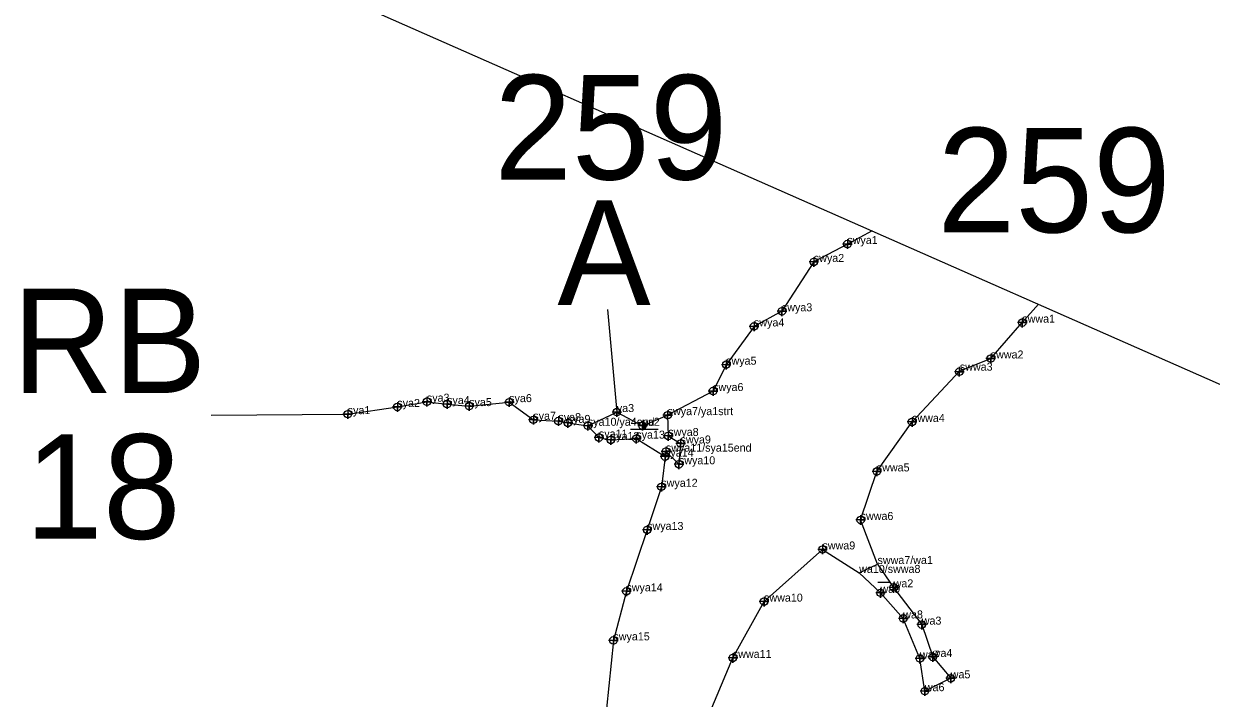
# Model space of a CAD drawing. Extents: x 2071991 to 2268989, y 436479 to 469629.
# Drawn here: x 2217583 to 2218325, y 438941 to 439363 of the extents above; entities that cross this region are included whole.
import ezdxf

# ---------------------------------------------------------------- set-up
doc = ezdxf.new("R2010")
doc.units = 0
for name, color, linetype in [('approx_PSA', 7, 'Continuous'), ('Default', 7, 'Continuous'), ('Exist Environmental Wetland Boundary', 7, 'Continuous'), ('Exist Environmental Wetland Boundary Cogo Comment', 7, 'Continuous'), ('Exist Environmental Wetland Boundary Cogo Point CELL', 7, 'Continuous'), ('Exist Hydro Jurisdictional Stream or Body of Water NEU Mitigable', 7, 'Continuous'), ('Exist Hydro Jurisdictional Stream or Body of Water NEU Mitigable Cogo Comment', 7, 'Continuous'), ('Exist Hydro Jurisdictional Stream or Body of Water NEU Mitigable Cogo Point CELL', 7, 'Continuous'), ('Exist Hydro Jurisdictional Stream or Body of Water NEU NonMitigable', 7, 'Continuous'), ('Exist Hydro Jurisdictional Stream or Body of Water NEU NonMitigable Cogo Comment', 7, 'Continuous'), ('Exist Hydro Jurisdictional Stream or Body of Water NEU NonMitigable Cogo Point CELL', 7, 'Continuous'), ('Exist Hydro Swamp or Marsh', 7, 'Continuous')]:
    doc.layers.add(name, color=color, linetype=linetype)

msp = doc.modelspace()

# ---------------------------------------------------------------- linework, layer by layer
at = {"layer": 'approx_PSA'}
msp.add_line((2217672.23, 439428.18), (2218953.94, 438862.92), dxfattribs=at)
at = {"layer": 'Default'}
for p, q in [((2217947.78, 439184.45), (2217953.67, 439120.41)), ((2217700.06, 439118.54), (2217785.49, 439119.1))]:
    msp.add_line(p, q, dxfattribs=at)
at = {"layer": 'Exist Environmental Wetland Boundary'}
for points in [[(2217935.6, 439111.83), (2217953.67, 439120.41), (2217969.69, 439111.83), (2217985.43, 439118.48)], [(2218116.61, 439025.41), (2218126.67, 439010.81), (2218144.24, 438987.52), (2218151.09, 438967.28), (2218162.35, 438953.95), (2218146.17, 438945.9), (2218143.11, 438966.31), (2218132.69, 438991.39), (2218118.45, 439007.36), (2218105.13, 439019.85)]]:
    msp.add_lwpolyline(points, dxfattribs=at)
at = {"layer": 'Exist Environmental Wetland Boundary Cogo Point CELL'}
for points in [[(2217953.67, 439123.41), (2217953.67, 439117.41), (2217953.67, 439120.41), (2217956.67, 439120.41), (2217950.67, 439120.41)], [(2217985.43, 439121.48), (2217985.43, 439115.48), (2217985.43, 439118.48), (2217988.43, 439118.48), (2217982.43, 439118.48)], [(2217935.6, 439114.83), (2217935.6, 439108.83), (2217935.6, 439111.83), (2217938.6, 439111.83), (2217932.6, 439111.83)], [(2217969.69, 439114.83), (2217969.69, 439108.83), (2217969.69, 439111.83), (2217972.69, 439111.83), (2217966.69, 439111.83)], [(2218118.45, 439010.36), (2218118.45, 439004.36), (2218118.45, 439007.36), (2218121.45, 439007.36), (2218115.45, 439007.36)], [(2218126.67, 439013.81), (2218126.67, 439007.81), (2218126.67, 439010.81), (2218129.67, 439010.81), (2218123.67, 439010.81)], [(2218132.69, 438994.39), (2218132.69, 438988.39), (2218132.69, 438991.39), (2218135.69, 438991.39), (2218129.69, 438991.39)], [(2218144.24, 438990.52), (2218144.24, 438984.52), (2218144.24, 438987.52), (2218147.24, 438987.52), (2218141.24, 438987.52)], [(2218143.11, 438969.31), (2218143.11, 438963.31), (2218143.11, 438966.31), (2218146.11, 438966.31), (2218140.11, 438966.31)], [(2218151.09, 438970.28), (2218151.09, 438964.28), (2218151.09, 438967.28), (2218154.09, 438967.28), (2218148.09, 438967.28)], [(2218162.35, 438956.95), (2218162.35, 438950.95), (2218162.35, 438953.95), (2218165.35, 438953.95), (2218159.35, 438953.95)], [(2218146.17, 438948.9), (2218146.17, 438942.9), (2218146.17, 438945.9), (2218149.17, 438945.9), (2218143.17, 438945.9)]]:
    msp.add_lwpolyline(points, dxfattribs=at)
for centre in [(2217953.67, 439120.41), (2217985.43, 439118.48), (2217935.6, 439111.83), (2217969.69, 439111.83), (2218118.45, 439007.36), (2218126.67, 439010.81), (2218132.69, 438991.39), (2218144.24, 438987.52), (2218143.11, 438966.31), (2218151.09, 438967.28), (2218162.35, 438953.95), (2218146.17, 438945.9)]:
    msp.add_circle(centre, 2.34, dxfattribs=at)
at = {"layer": 'Exist Hydro Jurisdictional Stream or Body of Water NEU Mitigable'}
msp.add_lwpolyline([(2217785.49, 439119.1), (2217816.49, 439123.6), (2217834.97, 439126.88), (2217847.6, 439125.41), (2217861.39, 439124.13), (2217886.41, 439126.61), (2217901.49, 439115.57), (2217917.15, 439114.79), (2217923.07, 439113.63), (2217935.6, 439111.83), (2217942.46, 439104.41), (2217949.93, 439102.96), (2217965.85, 439103.8), (2217983.84, 439092.54)], dxfattribs=at)
at = {"layer": 'Exist Hydro Jurisdictional Stream or Body of Water NEU Mitigable Cogo Point CELL'}
for points in [[(2217816.49, 439126.6), (2217816.49, 439120.6), (2217816.49, 439123.6), (2217819.49, 439123.6), (2217813.49, 439123.6)], [(2217834.97, 439129.88), (2217834.97, 439123.88), (2217834.97, 439126.88), (2217837.97, 439126.88), (2217831.97, 439126.88)], [(2217847.6, 439128.41), (2217847.6, 439122.41), (2217847.6, 439125.41), (2217850.6, 439125.41), (2217844.6, 439125.41)], [(2217861.39, 439127.13), (2217861.39, 439121.13), (2217861.39, 439124.13), (2217864.39, 439124.13), (2217858.39, 439124.13)], [(2217886.41, 439129.61), (2217886.41, 439123.61), (2217886.41, 439126.61), (2217889.41, 439126.61), (2217883.41, 439126.61)], [(2217785.49, 439122.1), (2217785.49, 439116.1), (2217785.49, 439119.1), (2217788.49, 439119.1), (2217782.49, 439119.1)], [(2217901.49, 439118.57), (2217901.49, 439112.57), (2217901.49, 439115.57), (2217904.49, 439115.57), (2217898.49, 439115.57)], [(2217917.15, 439117.79), (2217917.15, 439111.79), (2217917.15, 439114.79), (2217920.15, 439114.79), (2217914.15, 439114.79)], [(2217923.07, 439116.63), (2217923.07, 439110.63), (2217923.07, 439113.63), (2217926.07, 439113.63), (2217920.07, 439113.63)], [(2217942.46, 439107.41), (2217942.46, 439101.41), (2217942.46, 439104.41), (2217945.46, 439104.41), (2217939.46, 439104.41)], [(2217949.93, 439105.96), (2217949.93, 439099.96), (2217949.93, 439102.96), (2217952.93, 439102.96), (2217946.93, 439102.96)], [(2217965.85, 439106.8), (2217965.85, 439100.8), (2217965.85, 439103.8), (2217968.85, 439103.8), (2217962.85, 439103.8)], [(2217985.84, 439108.48), (2217985.84, 439102.48), (2217985.84, 439105.48), (2217988.84, 439105.48), (2217982.84, 439105.48)]]:
    msp.add_lwpolyline(points, dxfattribs=at)
for centre in [(2217834.97, 439126.88), (2217847.6, 439125.41), (2217861.39, 439124.13), (2217886.41, 439126.61), (2217785.49, 439119.1), (2217816.49, 439123.6), (2217901.49, 439115.57), (2217917.15, 439114.79), (2217923.07, 439113.63), (2217942.46, 439104.41), (2217949.93, 439102.96), (2217965.85, 439103.8), (2217985.84, 439105.48)]:
    msp.add_circle(centre, 2.34, dxfattribs=at)
at = {"layer": 'Exist Hydro Jurisdictional Stream or Body of Water NEU NonMitigable'}
for points in [[(2218113.17, 439233.72), (2218097.74, 439225.46), (2218076.79, 439214.25), (2218056.84, 439183.41), (2218039.4, 439173.95), (2218022, 439150.03), (2218013.84, 439133.54), (2217985.43, 439118.48), (2217985.84, 439105.48), (2217993.48, 439100.76), (2217992.49, 439087.76), (2217984.34, 439095.66)], [(2218012.02, 438933.04), (2218026.19, 438966.68), (2218045.69, 439001.9), (2218082.21, 439034.51), (2218105.13, 439019.85), (2218116.61, 439025.41), (2218106.05, 439052.94), (2218116.16, 439083.3), (2218138.17, 439114.21), (2218168.06, 439146.26), (2218187.36, 439153.91), (2218207.08, 439176.31), (2218217.22, 439187.83)], [(2217983.84, 439092.54), (2217984.34, 439095.66), (2217981.49, 439073.67), (2217972.61, 439046.71), (2217959.66, 439008.34), (2217951.55, 438977.67), (2217947.25, 438934.98)]]:
    msp.add_lwpolyline(points, dxfattribs=at)
at = {"layer": 'Exist Hydro Jurisdictional Stream or Body of Water NEU NonMitigable Cogo Point CELL'}
for points in [[(2218097.74, 439228.46), (2218097.74, 439222.46), (2218097.74, 439225.46), (2218100.74, 439225.46), (2218094.74, 439225.46)], [(2218076.79, 439217.25), (2218076.79, 439211.25), (2218076.79, 439214.25), (2218079.79, 439214.25), (2218073.79, 439214.25)], [(2218056.84, 439186.41), (2218056.84, 439180.41), (2218056.84, 439183.41), (2218059.84, 439183.41), (2218053.84, 439183.41)], [(2218207.08, 439179.31), (2218207.08, 439173.31), (2218207.08, 439176.31), (2218210.08, 439176.31), (2218204.08, 439176.31)], [(2218039.4, 439176.95), (2218039.4, 439170.95), (2218039.4, 439173.95), (2218042.4, 439173.95), (2218036.4, 439173.95)], [(2218187.36, 439156.91), (2218187.36, 439150.91), (2218187.36, 439153.91), (2218190.36, 439153.91), (2218184.36, 439153.91)], [(2218022, 439153.03), (2218022, 439147.03), (2218022, 439150.03), (2218025, 439150.03), (2218019, 439150.03)], [(2218167.71, 439148.62), (2218167.71, 439142.62), (2218167.71, 439145.62), (2218170.71, 439145.62), (2218164.71, 439145.62)], [(2218013.84, 439136.54), (2218013.84, 439130.54), (2218013.84, 439133.54), (2218016.84, 439133.54), (2218010.84, 439133.54)], [(2217985.43, 439121.48), (2217985.43, 439115.48), (2217985.43, 439118.48), (2217988.43, 439118.48), (2217982.43, 439118.48)], [(2218138.17, 439117.21), (2218138.17, 439111.21), (2218138.17, 439114.21), (2218141.17, 439114.21), (2218135.17, 439114.21)], [(2217985.84, 439108.48), (2217985.84, 439102.48), (2217985.84, 439105.48), (2217988.84, 439105.48), (2217982.84, 439105.48)], [(2217984.34, 439098.66), (2217984.34, 439092.66), (2217984.34, 439095.66), (2217987.34, 439095.66), (2217981.34, 439095.66)], [(2217993.48, 439103.76), (2217993.48, 439097.76), (2217993.48, 439100.76), (2217996.48, 439100.76), (2217990.48, 439100.76)], [(2217983.84, 439095.54), (2217983.84, 439089.54), (2217983.84, 439092.54), (2217986.84, 439092.54), (2217980.84, 439092.54)], [(2217992.49, 439090.76), (2217992.49, 439084.76), (2217992.49, 439087.76), (2217995.49, 439087.76), (2217989.49, 439087.76)], [(2218116.16, 439086.3), (2218116.16, 439080.3), (2218116.16, 439083.3), (2218119.16, 439083.3), (2218113.16, 439083.3)], [(2217981.49, 439076.67), (2217981.49, 439070.67), (2217981.49, 439073.67), (2217984.49, 439073.67), (2217978.49, 439073.67)], [(2218106.05, 439055.94), (2218106.05, 439049.94), (2218106.05, 439052.94), (2218109.05, 439052.94), (2218103.05, 439052.94)], [(2217972.61, 439049.71), (2217972.61, 439043.71), (2217972.61, 439046.71), (2217975.61, 439046.71), (2217969.61, 439046.71)], [(2218082.21, 439037.51), (2218082.21, 439031.51), (2218082.21, 439034.51), (2218085.21, 439034.51), (2218079.21, 439034.51)], [(2217959.66, 439011.34), (2217959.66, 439005.34), (2217959.66, 439008.34), (2217962.66, 439008.34), (2217956.66, 439008.34)], [(2218045.69, 439004.9), (2218045.69, 438998.9), (2218045.69, 439001.9), (2218048.69, 439001.9), (2218042.69, 439001.9)], [(2217951.55, 438980.67), (2217951.55, 438974.67), (2217951.55, 438977.67), (2217954.55, 438977.67), (2217948.55, 438977.67)], [(2218026.19, 438969.68), (2218026.19, 438963.68), (2218026.19, 438966.68), (2218029.19, 438966.68), (2218023.19, 438966.68)]]:
    msp.add_lwpolyline(points, dxfattribs=at)
for centre in [(2218097.74, 439225.46), (2218076.79, 439214.25), (2218056.84, 439183.41), (2218207.08, 439176.31), (2218039.4, 439173.95), (2218187.36, 439153.91), (2218022, 439150.03), (2218167.71, 439145.62), (2218013.84, 439133.54), (2217985.43, 439118.48), (2218138.17, 439114.21), (2217985.84, 439105.48), (2217984.34, 439095.66), (2217993.48, 439100.76), (2217983.84, 439092.54), (2217992.49, 439087.76), (2218116.16, 439083.3), (2217981.49, 439073.67), (2218106.05, 439052.94), (2217972.61, 439046.71), (2218082.21, 439034.51), (2217959.66, 439008.34), (2218045.69, 439001.9), (2217951.55, 438977.67), (2218026.19, 438966.68)]:
    msp.add_circle(centre, 2.34, dxfattribs=at)
at = {"layer": 'Exist Hydro Swamp or Marsh'}
msp.add_line((2218116.85, 439014.1), (2218124.4, 439014.1), dxfattribs=at)
for points in [[(2217962.27, 439109.73), (2217970.87, 439109.73), (2217970.87, 439112.33)], [(2217970.87, 439112.33), (2217970.87, 439109.73), (2217979.47, 439109.73)]]:
    msp.add_lwpolyline(points, dxfattribs=at)
for centre, radius, start, end in [((2217958.6, 439108.84), 12.3, 4.14034, 15.62514), ((2217989.11, 439103.67), 19.22, 151.22853, 161.62219)]:
    msp.add_arc(centre, radius, start, end, dxfattribs=at)

# ---------------------------------------------------------------- texts
at = {"layer": 'Default'}
for s, p in [('259', (2217877.01, 439265.79)), ('259', (2218154.05, 439232.76)), ('A', (2217916.53, 439187.39)), ('RB', (2217575.85, 439132.31)), ('18', (2217583.89, 439041.16))]:
    msp.add_text(s, height=65.34, dxfattribs=at).set_placement(p)
at = {"layer": 'Exist Environmental Wetland Boundary Cogo Comment'}
for s, p in [('ya3', (2217953.67, 439120.41)), ('ya2', (2217969.69, 439111.83)), ('wa2', (2218126.67, 439010.81)), ('wa9', (2218118.45, 439007.36)), ('wa8', (2218132.69, 438991.39)), ('wa3', (2218144.24, 438987.52)), ('wa7', (2218143.11, 438966.31)), ('wa4', (2218151.09, 438967.28)), ('wa5', (2218162.35, 438953.95)), ('wa6', (2218146.17, 438945.9))]:
    msp.add_text(s, height=5, dxfattribs=at).set_placement(p)
at = {"layer": 'Exist Hydro Jurisdictional Stream or Body of Water NEU Mitigable Cogo Comment'}
for s, p in [('sya2', (2217816.49, 439123.6)), ('sya3', (2217834.97, 439126.88)), ('sya4', (2217847.6, 439125.41)), ('sya5', (2217861.39, 439124.13)), ('sya6', (2217886.41, 439126.61)), ('sya1', (2217785.49, 439119.1)), ('sya7', (2217901.49, 439115.57)), ('sya8', (2217917.15, 439114.79)), ('sya9', (2217923.07, 439113.63)), ('sya10/ya4end', (2217935.6, 439111.83)), ('sya11', (2217942.46, 439104.41)), ('sya12', (2217949.93, 439102.96)), ('sya13', (2217965.85, 439103.8))]:
    msp.add_text(s, height=5, dxfattribs=at).set_placement(p)
at = {"layer": 'Exist Hydro Jurisdictional Stream or Body of Water NEU NonMitigable Cogo Comment'}
for s, p in [('swya1', (2218097.74, 439225.46)), ('swya2', (2218076.79, 439214.25)), ('swya3', (2218056.84, 439183.41)), ('swya4', (2218039.4, 439173.95)), ('swwa1', (2218207.08, 439176.31)), ('swwa2', (2218187.36, 439153.91)), ('swya5', (2218022, 439150.03)), ('swwa3', (2218168.06, 439146.26)), ('swya6', (2218013.84, 439133.54)), ('swya7/ya1strt', (2217985.43, 439118.48)), ('swwa4', (2218138.17, 439114.21)), ('swya8', (2217985.84, 439105.48)), ('swya9', (2217993.48, 439100.76)), ('sya14', (2217983.82, 439092.6)), ('swya11/sya15end', (2217984.34, 439095.66)), ('swya10', (2217992.49, 439087.76)), ('swwa5', (2218116.16, 439083.3)), ('swya12', (2217981.49, 439073.67)), ('swwa6', (2218106.05, 439052.94)), ('swya13', (2217972.61, 439046.71)), ('swwa9', (2218082.21, 439034.51)), ('swwa7/wa1', (2218116.61, 439025.41)), ('wa10/swwa8', (2218105.13, 439019.85)), ('swya14', (2217959.66, 439008.34)), ('swwa10', (2218045.69, 439001.9)), ('swya15', (2217951.55, 438977.67)), ('swwa11', (2218026.19, 438966.68))]:
    msp.add_text(s, height=5, dxfattribs=at).set_placement(p)

doc.saveas('drawing.dxf')
